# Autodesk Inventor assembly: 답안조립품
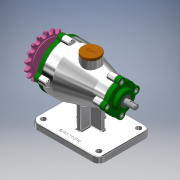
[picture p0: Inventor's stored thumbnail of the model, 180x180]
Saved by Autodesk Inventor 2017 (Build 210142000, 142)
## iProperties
Part Number: 답안조립품
Material: 일반
Document SubType Name: Assembly
Designer: 222
Author: 222
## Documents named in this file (15)
- C:\Users\222\Desktop\701206V1008\701206V1008\답안조립품.iam
- C:\Users\222\Desktop\701206V1008\본체.ipt
- C:\Users\222\Desktop\701206V1008\701206V1008\개스킷 A.ipt
- C:\Users\222\Desktop\701206V1008\701206V1008\개스킷 B.ipt
- C:\Users\222\Desktop\701206V1008\701206V1008\뒤커버.ipt
- C:\Users\222\Desktop\701206V1008\701206V1008\마개.ipt
- C:\Users\222\Desktop\701206V1008\701206V1008\베어링 6200.ipt
- C:\Users\222\Desktop\701206V1008\701206V1008\베어링 6203.ipt
- C:\Users\222\Desktop\701206V1008\701206V1008\볼트 M5.ipt
- C:\Users\222\Desktop\701206V1008\701206V1008\스프로킷.ipt
- C:\Users\222\Desktop\701206V1008\701206V1008\앞커버.ipt
- C:\Users\222\Desktop\701206V1008\701206V1008\오일 실 10 20 7.ipt
- C:\Users\222\Desktop\701206V1008\701206V1008\오일 실 17 30 8.ipt
- C:\Users\222\Desktop\701206V1008\701206V1008\축.ipt
- C:\Users\222\Desktop\701206V1008\701206V1008\키 4x4x14.ipt
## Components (2 placed, 2 different names)
1. 개스킷 A:1
2. 개스킷 B:1
